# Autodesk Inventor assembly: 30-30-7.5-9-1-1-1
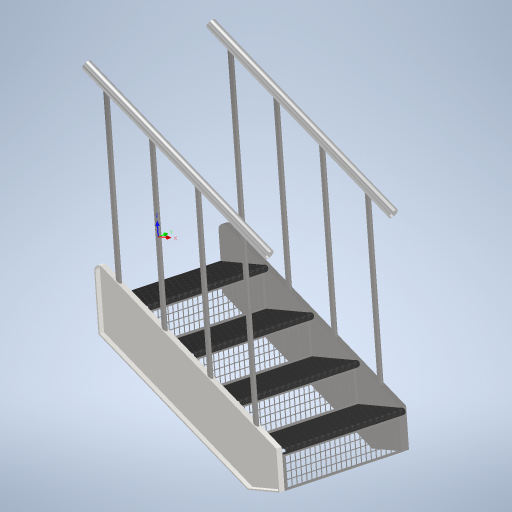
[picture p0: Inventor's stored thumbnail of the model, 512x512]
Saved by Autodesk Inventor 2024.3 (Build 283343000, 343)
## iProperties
RuleStatus: InUse
Company: Elevation Stair Company
AfterAnyUserParamChange0: Type Name
Created: 2026-01
Part Number: 30-30-7.5-9-1-1-1
Description: Metal Stairs
Document SubType Name: Assembly
Designer: MichelleRasmussen
Run: 9.000 in
TheAngle: 39.81 deg
TargetRise: 7.250 in
Rise: 7.500 in
Height: 30.000 in
Width: 30.000 in
StringerWidth: 10.000 in
StringerThickness: 1.500 in
StringerLength: 46.861 in
NumberOfSteps: 5.000 ul
Length: 36.000 in
TreadThickness: 1.250 in
StringerStockLength: 48.000 in
RailingStockLength: 46.861 in
RailingWidth: 3.000 in
RailingThickness: 2.000 in
RightRail: True
LeftRail: True
StringerMaterial: Steel, Galvanized
TreadMaterial: Steel, Wrought
RiserMaterial: Steel, Galvanized
BalusterMaterial: Steel, Galvanized
HandrailMaterial: Aluminum 6061
HasHandrail: True
HasRiser: True
BalusterLength: 36.000 in
BalusterDia: 1.000 in
INDDataset: sample
Author: MichelleRasmussen
Created: 2022-06
Designer: David Reaume
Author: David Reaume
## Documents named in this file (14)
- C:\Users\MichelleRasmussen\OneDrive\Documents\AutodeskTraining\Autodesk\Informed Design\Staircase Sample1\Staircase Sample\Staircase Sample.iam
- C:\Users\MichelleRasmussen\OneDrive\Documents\AutodeskTraining\Autodesk\Informed Design\Staircase Sample1\Staircase Sample\Stringer.ipt
- C:\Users\MichelleRasmussen\OneDrive\Documents\AutodeskTraining\Autodesk\Informed Design\Staircase Sample1\Staircase Sample\Tread.ipt
- C:\Users\MichelleRasmussen\OneDrive\Documents\AutodeskTraining\Autodesk\Informed Design\Staircase Sample1\Staircase Sample\Riser.ipt
- C:\Users\MichelleRasmussen\OneDrive\Documents\AutodeskTraining\Autodesk\Informed Design\Staircase Sample1\Staircase Sample\Baluster.ipt
- C:\Users\MichelleRasmussen\OneDrive\Documents\AutodeskTraining\Autodesk\Informed Design\Staircase Sample1\Staircase Sample\Railing.ipt
- C:\Users\MichelleRasmussen\OneDrive\Documents\AutodeskTraining\Autodesk\Informed Design\Staircase Sample1\Staircase Sample\Left Stringer_MIR.ipt
- C:\Users\partonj\Desktop\JP\Inventor Datasets\IND Samples (Analytics ID Added)\Inventor 2024\Staircase Sample1\Staircase Sample\Stringer.ipt
- C:\Users\partonj\Desktop\JP\Inventor Datasets\IND Samples (Analytics ID Added)\Inventor 2024\Staircase Sample1\Staircase Sample\Tread.ipt
- C:\Users\partonj\Desktop\JP\Inventor Datasets\IND Samples (Analytics ID Added)\Inventor 2024\Staircase Sample1\Staircase Sample\Riser.ipt
- C:\Users\partonj\Desktop\JP\Inventor Datasets\IND Samples (Analytics ID Added)\Inventor 2024\Staircase Sample1\Staircase Sample\Baluster.ipt
- C:\Users\partonj\Desktop\JP\Inventor Datasets\IND Samples (Analytics ID Added)\Inventor 2024\Staircase Sample1\Staircase Sample\Railing.ipt
- C:\Users\partonj\Desktop\JP\Inventor Datasets\IND Samples (Analytics ID Added)\Inventor 2024\Staircase Sample1\Staircase Sample\Left Stringer_MIR.ipt
- C:\Users\MichelleRasmussen\OneDrive\Documents\AutodeskTraining\Autodesk\Informed Design\Staircase Sample1\Staircase Sample\Staircase Sample_Simplify_1.ipt
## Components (20 placed, 7 different names)
1. Stringer
2. Left Stringer_MIR:1
3. Right Railing
4. Left Railing — Flush:7, Flush:8, Flush:9
5. Tread:1
6. Tread:2
7. Tread:3
8. Tread:4
9. Riser:1
10. Riser:2
11. Riser:3
12. Riser:4
13. Baluster:1
14. Baluster:12
15. Baluster:15
16. Baluster:17
17. Baluster:7 — Flush:11, Flush:12
18. Baluster:8
19. Baluster:13
20. Baluster:16
## Component patterns: Tread Pattern (4 elements), Riser Pattern (4 elements), Right Baluster Pattern (4 elements), Left Baluster Pattern (4 elements)
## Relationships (5: Flush 5)
- Flush:7: Left Railing
- Flush:8: Left Railing
- Flush:9: Left Railing
- Flush:11: Baluster:7
- Flush:12: Baluster:7
## Named parameters: TheAngle = 6.94738 mm, StringerThickness = 38.1 mm, StringerLength = 1190.28205 mm, Length = 914.4 mm, TheAngleRounded = 6.94816 mm, StringerStockLength = 1219.2 mm, DiagonalTreadSpacing = 297.57051 mm, BalusterDia = 25.4 mm, BalusterLength = 914.4 mm, RailingStockLength = 1190.28205 mm, RailingWidth = 76.2 mm, RailingThickness = 50.8 mm, StringerSpacing = 876.3 mm
